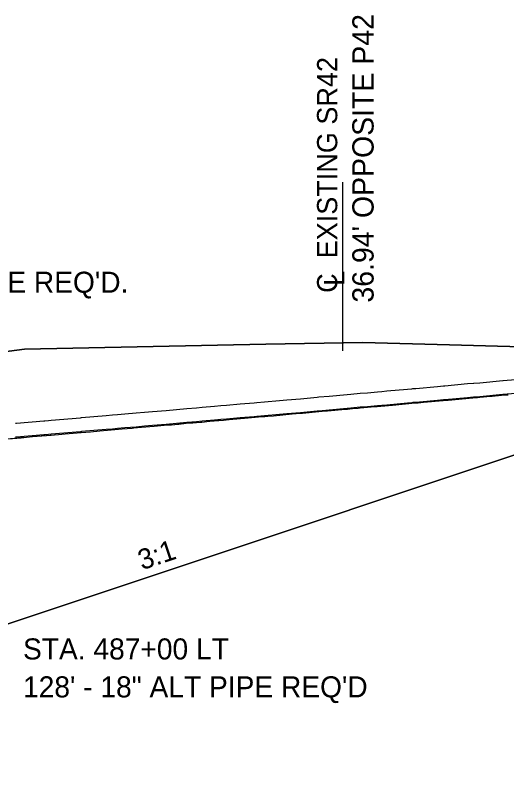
# Model space of a CAD drawing. Extents: x -100 to 4303, y -13 to 10775.
# Drawn here: x 3101.4 to 3118.89, y 5512.2 to 5539.77 of the extents above; entities that cross this region are included whole.
import ezdxf

# ---------------------------------------------------------------- set-up
doc = ezdxf.new("R2010")
doc.units = 0
for name, color, linetype in [('DTM_P_FINISHED_GRADE', 7, 'Continuous'), ('DTM_X_GROUND', 7, 'Continuous'), ('XS_M_SHAPES_EARTHWORK', 7, 'Continuous'), ('XS_P_DR_GRAVEL', 7, 'Continuous'), ('XS_P_DRAINAGE', 7, 'Continuous'), ('XS_P_GROUND', 7, 'Continuous'), ('XS_P_TX_CLEARZONE', 7, 'Continuous'), ('XS_P_TX_FS_BS', 7, 'Continuous'), ('XS_X_EXCESS', 7, 'Continuous')]:
    doc.layers.add(name, color=color, linetype=linetype)

msp = doc.modelspace()

# ---------------------------------------------------------------- linework, layer by layer
at = {"layer": 'DTM_P_FINISHED_GRADE'}
for points in [[(3101.397, 5525.247), (3101.435, 5525.25), (3101.437, 5525.25), (3102.404, 5525.331), (3102.44, 5525.334), (3102.575, 5525.346), (3102.665, 5525.354), (3103.714, 5525.442), (3103.747, 5525.445), (3104.63, 5525.518), (3104.853, 5525.539), (3105.026, 5525.554), (3105.29, 5525.576), (3105.7, 5525.61), (3105.992, 5525.637), (3106.278, 5525.661), (3106.771, 5525.702), (3107.13, 5525.736), (3107.507, 5525.767), (3107.843, 5525.795), (3108.049, 5525.815), (3108.49, 5525.851), (3108.713, 5525.872), (3108.917, 5525.889), (3109.402, 5525.935), (3109.897, 5525.976), (3109.991, 5525.984), (3110.263, 5526.006), (3110.807, 5526.057), (3111.062, 5526.078), (3111.066, 5526.079), (3111.546, 5526.118), (3112.14, 5526.174), (3112.209, 5526.18), (3112.572, 5526.21), (3113.215, 5526.27), (3113.339, 5526.28), (3113.68, 5526.312), (3113.937, 5526.333), (3114.288, 5526.366), (3114.453, 5526.379), (3114.63, 5526.394), (3115.36, 5526.462), (3115.513, 5526.474), (3115.553, 5526.478), (3115.66, 5526.486), (3116.431, 5526.558), (3116.639, 5526.575), (3116.692, 5526.579), (3117.499, 5526.654), (3117.713, 5526.671), (3117.724, 5526.672), (3117.934, 5526.689), (3118.756, 5526.765), (3118.776, 5526.767), (3119.206, 5526.806)], [(3101.397, 5525.247), (3101.435, 5525.25), (3101.437, 5525.25), (3102.404, 5525.331), (3102.44, 5525.334), (3102.575, 5525.346), (3102.665, 5525.354), (3103.714, 5525.442), (3103.747, 5525.445), (3104.63, 5525.518), (3104.853, 5525.539), (3105.026, 5525.554), (3105.29, 5525.576), (3105.7, 5525.61), (3105.992, 5525.637), (3106.278, 5525.661), (3106.771, 5525.702), (3107.13, 5525.736), (3107.507, 5525.767), (3107.843, 5525.795), (3108.049, 5525.815), (3108.49, 5525.851), (3108.713, 5525.872), (3108.917, 5525.889), (3109.402, 5525.935), (3109.897, 5525.976), (3109.991, 5525.984), (3110.263, 5526.006), (3110.807, 5526.057), (3111.062, 5526.078), (3111.066, 5526.079), (3111.546, 5526.118), (3112.14, 5526.174), (3112.209, 5526.18), (3112.572, 5526.21), (3113.215, 5526.27), (3113.339, 5526.28), (3113.68, 5526.312), (3113.937, 5526.333), (3114.288, 5526.366), (3114.453, 5526.379), (3114.63, 5526.394), (3115.36, 5526.462), (3115.513, 5526.474), (3115.553, 5526.478), (3115.66, 5526.486), (3116.431, 5526.558), (3116.639, 5526.575), (3116.692, 5526.579), (3117.499, 5526.654), (3117.713, 5526.671), (3117.724, 5526.672), (3117.934, 5526.689), (3118.756, 5526.765), (3118.776, 5526.767), (3119.206, 5526.806)], [(3100.649, 5524.651), (3101.598, 5524.73), (3101.788, 5524.748), (3101.898, 5524.757), (3102.006, 5524.767), (3102.793, 5524.833), (3102.927, 5524.845), (3103.163, 5524.865), (3103.737, 5524.913), (3104.066, 5524.944), (3104.403, 5524.972), (3104.809, 5525.006), (3105.203, 5525.043), (3105.553, 5525.072), (3105.619, 5525.077), (3105.882, 5525.099), (3106.339, 5525.142), (3106.813, 5525.182), (3106.956, 5525.193), (3107.473, 5525.242), (3107.987, 5525.285), (3108.031, 5525.288), (3108.311, 5525.315), (3108.813, 5525.356), (3109.105, 5525.384), (3109.143, 5525.387), (3109.56, 5525.421), (3110.18, 5525.479), (3110.28, 5525.487), (3110.388, 5525.496), (3110.587, 5525.513), (3111.254, 5525.575), (3111.402, 5525.587), (3111.616, 5525.605), (3112.327, 5525.671), (3112.508, 5525.686), (3112.646, 5525.697), (3113.398, 5525.767), (3113.6, 5525.784), (3113.677, 5525.79), (3114.065, 5525.826), (3114.286, 5525.844), (3114.68, 5525.88), (3114.709, 5525.883), (3114.823, 5525.892), (3115.639, 5525.967), (3115.741, 5525.976), (3115.748, 5525.976), (3115.934, 5525.991), (3116.773, 5526.068), (3116.806, 5526.071), (3116.936, 5526.081), (3117.804, 5526.161), (3117.854, 5526.165), (3117.94, 5526.172), (3118.835, 5526.253), (3118.893, 5526.258)]]:
    msp.add_lwpolyline(points, dxfattribs=at)
at = {"layer": 'DTM_X_GROUND'}
msp.add_lwpolyline([(3000, 5512.2), (3044.132, 5513.453), (3046.486, 5513.62), (3053.808, 5513.95), (3070.909, 5514.966), (3077.153, 5518.209), (3097.118, 5527.209), (3098.789, 5527.5), (3101.713, 5527.882), (3110.312, 5528.066), (3113.777, 5528.123), (3116.864, 5528.039), (3124.572, 5527.826)], dxfattribs=at)
at = {"layer": 'XS_M_SHAPES_EARTHWORK'}
msp.add_lwpolyline([(3070.973, 5514.999), (3077.153, 5518.209), (3097.118, 5527.209), (3098.789, 5527.5), (3101.713, 5527.882), (3110.312, 5528.066), (3113.777, 5528.123), (3116.864, 5528.039), (3124.572, 5527.826), (3125.877, 5527.605), (3129.562, 5526.928), (3131.005, 5526.033), (3126.052, 5525.901), (3120, 5524.389), (3093.161, 5515.443)], close=True, dxfattribs=at)
at = {"layer": 'XS_P_DR_GRAVEL'}
for points in [[(3101.435, 5525.25), (3101.437, 5525.25), (3102.404, 5525.331), (3102.44, 5525.334), (3102.575, 5525.346), (3102.665, 5525.354), (3103.714, 5525.442), (3103.747, 5525.445), (3104.63, 5525.518), (3104.853, 5525.539), (3105.026, 5525.554), (3105.29, 5525.576), (3105.7, 5525.61), (3105.992, 5525.637), (3106.278, 5525.661), (3106.771, 5525.702), (3107.13, 5525.736), (3107.507, 5525.767), (3107.843, 5525.795), (3108.049, 5525.815), (3108.49, 5525.851), (3108.713, 5525.872), (3108.917, 5525.889), (3109.402, 5525.935), (3109.897, 5525.976), (3109.991, 5525.984), (3110.263, 5526.006), (3110.807, 5526.057), (3111.062, 5526.078), (3111.066, 5526.079), (3111.546, 5526.118), (3112.14, 5526.174), (3112.209, 5526.18), (3112.572, 5526.21), (3113.215, 5526.27), (3113.339, 5526.28), (3113.68, 5526.312), (3113.937, 5526.333), (3114.288, 5526.366), (3114.453, 5526.379), (3114.63, 5526.394), (3115.36, 5526.462), (3115.513, 5526.474), (3115.553, 5526.478), (3115.66, 5526.486), (3116.431, 5526.558), (3116.639, 5526.575), (3116.692, 5526.579), (3117.499, 5526.654), (3117.713, 5526.671), (3117.724, 5526.672), (3117.934, 5526.689), (3118.756, 5526.765), (3118.776, 5526.767), (3119.206, 5526.806)], [(3101.435, 5525.25), (3101.437, 5525.25), (3102.404, 5525.331), (3102.44, 5525.334), (3102.575, 5525.346), (3102.665, 5525.354), (3103.714, 5525.442), (3103.747, 5525.445), (3104.63, 5525.518), (3104.853, 5525.539), (3105.026, 5525.554), (3105.29, 5525.576), (3105.7, 5525.61), (3105.992, 5525.637), (3106.278, 5525.661), (3106.771, 5525.702), (3107.13, 5525.736), (3107.507, 5525.767), (3107.843, 5525.795), (3108.049, 5525.815), (3108.49, 5525.851), (3108.713, 5525.872), (3108.917, 5525.889), (3109.402, 5525.935), (3109.897, 5525.976), (3109.991, 5525.984), (3110.263, 5526.006), (3110.807, 5526.057), (3111.062, 5526.078), (3111.066, 5526.079), (3111.546, 5526.118), (3112.14, 5526.174), (3112.209, 5526.18), (3112.572, 5526.21), (3113.215, 5526.27), (3113.339, 5526.28), (3113.68, 5526.312), (3113.937, 5526.333), (3114.288, 5526.366), (3114.453, 5526.379), (3114.63, 5526.394), (3115.36, 5526.462), (3115.513, 5526.474), (3115.553, 5526.478), (3115.66, 5526.486), (3116.431, 5526.558), (3116.639, 5526.575), (3116.692, 5526.579), (3117.499, 5526.654), (3117.713, 5526.671), (3117.724, 5526.672), (3117.934, 5526.689), (3118.756, 5526.765), (3118.776, 5526.767), (3119.206, 5526.806)], [(3119.206, 5526.306), (3118.776, 5526.267), (3118.756, 5526.265), (3117.934, 5526.189), (3117.724, 5526.172), (3117.713, 5526.171), (3117.499, 5526.154), (3116.692, 5526.079), (3116.639, 5526.075), (3116.431, 5526.058), (3115.66, 5525.986), (3115.553, 5525.978), (3115.513, 5525.974), (3115.36, 5525.962), (3114.63, 5525.894), (3114.453, 5525.879), (3114.288, 5525.866), (3113.937, 5525.833), (3113.68, 5525.812), (3113.339, 5525.78), (3113.215, 5525.77), (3112.572, 5525.71), (3112.209, 5525.68), (3112.14, 5525.674), (3111.546, 5525.618), (3111.066, 5525.579), (3111.062, 5525.578), (3110.807, 5525.557), (3110.263, 5525.506), (3109.991, 5525.484), (3109.897, 5525.476), (3109.402, 5525.435), (3108.917, 5525.389), (3108.713, 5525.372), (3108.49, 5525.351), (3108.049, 5525.315), (3107.843, 5525.295), (3107.507, 5525.267), (3107.13, 5525.236), (3106.771, 5525.202), (3106.278, 5525.161), (3105.992, 5525.137), (3105.7, 5525.11), (3105.29, 5525.076), (3105.026, 5525.054), (3104.853, 5525.039), (3104.63, 5525.018), (3103.747, 5524.945), (3103.714, 5524.942), (3102.665, 5524.854), (3102.575, 5524.846), (3102.44, 5524.834), (3102.404, 5524.831), (3101.437, 5524.75), (3101.435, 5524.75), (3101.397, 5524.747)], [(3119.206, 5526.306), (3118.776, 5526.267), (3118.756, 5526.265), (3117.934, 5526.189), (3117.724, 5526.172), (3117.713, 5526.171), (3117.499, 5526.154), (3116.692, 5526.079), (3116.639, 5526.075), (3116.431, 5526.058), (3115.66, 5525.986), (3115.553, 5525.978), (3115.513, 5525.974), (3115.36, 5525.962), (3114.63, 5525.894), (3114.453, 5525.879), (3114.288, 5525.866), (3113.937, 5525.833), (3113.68, 5525.812), (3113.339, 5525.78), (3113.215, 5525.77), (3112.572, 5525.71), (3112.209, 5525.68), (3112.14, 5525.674), (3111.546, 5525.618), (3111.066, 5525.579), (3111.062, 5525.578), (3110.807, 5525.557), (3110.263, 5525.506), (3109.991, 5525.484), (3109.897, 5525.476), (3109.402, 5525.435), (3108.917, 5525.389), (3108.713, 5525.372), (3108.49, 5525.351), (3108.049, 5525.315), (3107.843, 5525.295), (3107.507, 5525.267), (3107.13, 5525.236), (3106.771, 5525.202), (3106.278, 5525.161), (3105.992, 5525.137), (3105.7, 5525.11), (3105.29, 5525.076), (3105.026, 5525.054), (3104.853, 5525.039), (3104.63, 5525.018), (3103.747, 5524.945), (3103.714, 5524.942), (3102.665, 5524.854), (3102.575, 5524.846), (3102.44, 5524.834), (3102.404, 5524.831), (3101.437, 5524.75), (3101.435, 5524.75), (3101.397, 5524.747)], [(3101.397, 5525.247), (3101.435, 5525.25)], [(3101.397, 5525.247), (3101.435, 5525.25)]]:
    msp.add_lwpolyline(points, dxfattribs=at)
at = {"layer": 'XS_P_GROUND'}
msp.add_lwpolyline([(3093.161, 5515.443), (3120, 5524.389), (3120, 5524.389), (3120, 5524.389), (3132, 5527.389)], dxfattribs=at)
at = {"layer": 'XS_P_TX_CLEARZONE'}
msp.add_line((3113.06, 5527.829), (3113.06, 5533.829), dxfattribs=at)
at = {"layer": 'XS_X_EXCESS'}
for p, q in [((3115.934, 5525.991), (3116.773, 5526.068)), ((3116.773, 5526.068), (3116.806, 5526.071)), ((3116.806, 5526.071), (3116.936, 5526.081)), ((3116.936, 5526.081), (3117.804, 5526.161)), ((3117.804, 5526.161), (3117.854, 5526.165)), ((3111.616, 5525.605), (3112.327, 5525.671)), ((3113.398, 5525.767), (3113.6, 5525.784)), ((3113.6, 5525.784), (3113.677, 5525.79)), ((3110.18, 5525.479), (3110.28, 5525.487)), ((3111.402, 5525.587), (3111.616, 5525.605)), ((3106.339, 5525.142), (3106.813, 5525.182)), ((3106.813, 5525.182), (3106.956, 5525.193)), ((3102.006, 5524.767), (3102.667, 5524.822)), ((3102.667, 5524.822), (3102.793, 5524.833)), ((3102.793, 5524.833), (3102.927, 5524.845)), ((3103.737, 5524.913), (3104.066, 5524.944)), ((3104.809, 5525.006), (3105.203, 5525.043)), ((3105.203, 5525.043), (3105.553, 5525.072)), ((3101.788, 5524.748), (3101.898, 5524.757)), ((3101.898, 5524.757), (3102.006, 5524.767))]:
    msp.add_line(p, q, dxfattribs=at)
for points in [[(3129.815, 5526.77), (3129.562, 5526.928), (3125.877, 5527.605), (3124.572, 5527.826), (3116.864, 5528.039), (3113.777, 5528.123), (3110.312, 5528.066), (3101.713, 5527.882), (3098.789, 5527.5), (3097.118, 5527.209), (3080.966, 5519.928)], [(3117.854, 5526.165), (3117.94, 5526.173), (3118.302, 5526.206), (3118.382, 5526.212), (3118.835, 5526.253)], [(3118.835, 5526.253), (3118.893, 5526.258), (3118.945, 5526.262)], [(3114.072, 5525.826), (3114.286, 5525.846), (3114.468, 5525.863), (3114.68, 5525.88), (3114.709, 5525.883), (3114.823, 5525.892), (3115.639, 5525.967)], [(3115.639, 5525.967), (3115.741, 5525.976), (3115.934, 5525.991)], [(3112.327, 5525.671), (3112.508, 5525.686), (3112.646, 5525.697)], [(3112.646, 5525.697), (3113.015, 5525.732), (3113.021, 5525.732)], [(3113.021, 5525.732), (3113.223, 5525.751), (3113.398, 5525.767)], [(3113.677, 5525.79), (3114.065, 5525.826), (3114.072, 5525.826)], [(3108.315, 5525.315), (3108.605, 5525.342), (3108.813, 5525.359), (3109.105, 5525.384), (3109.143, 5525.387)], [(3109.143, 5525.387), (3109.56, 5525.421), (3110.18, 5525.479)], [(3110.28, 5525.487), (3110.388, 5525.496), (3110.587, 5525.513), (3111.254, 5525.575), (3111.402, 5525.587)], [(3105.553, 5525.072), (3105.619, 5525.077), (3105.882, 5525.099), (3106.339, 5525.142)], [(3106.956, 5525.193), (3107.208, 5525.217), (3107.212, 5525.217)], [(3107.212, 5525.217), (3107.473, 5525.242), (3107.721, 5525.263)], [(3107.721, 5525.263), (3107.987, 5525.285), (3108.031, 5525.288), (3108.311, 5525.315), (3108.315, 5525.315)], [(3102.927, 5524.845), (3103.163, 5524.865), (3103.737, 5524.913)], [(3104.066, 5524.944), (3104.403, 5524.972), (3104.809, 5525.006)], [(3100.607, 5524.647), (3100.649, 5524.651), (3100.714, 5524.657), (3101.598, 5524.731), (3101.69, 5524.738), (3101.788, 5524.748)]]:
    msp.add_lwpolyline(points, dxfattribs=at)

# ---------------------------------------------------------------- texts
at = {"layer": 'XS_P_DRAINAGE'}
for s, p in [('128\' - 18" ALT PIPE REQ\'D.', (3092.864, 5529.891)), ('STA. 487+00 LT', (3101.666, 5516.831)), ('128\' - 18" ALT PIPE REQ\'D', (3101.666, 5515.481))]:
    msp.add_text(s, height=0.75, dxfattribs=at).set_placement(p)
at = {"layer": 'XS_P_TX_CLEARZONE'}
for s, height, p in [("36.94' OPPOSITE P42", 0.75778, (3114.155, 5529.541)), ('C  EXISTING SR42', 0.72, (3112.86, 5529.887)), ('L', 0.72, (3113.11, 5530.138)), ('L', 0.72, (3113.11, 5530.138))]:
    msp.add_text(s, height=height, rotation=90, dxfattribs=at).set_placement(p)
at = {"layer": 'XS_P_TX_FS_BS'}
msp.add_text('3:1', height=0.72, rotation=18.4332, dxfattribs=at).set_placement((3105.905, 5520.007))

doc.saveas('drawing.dxf')
